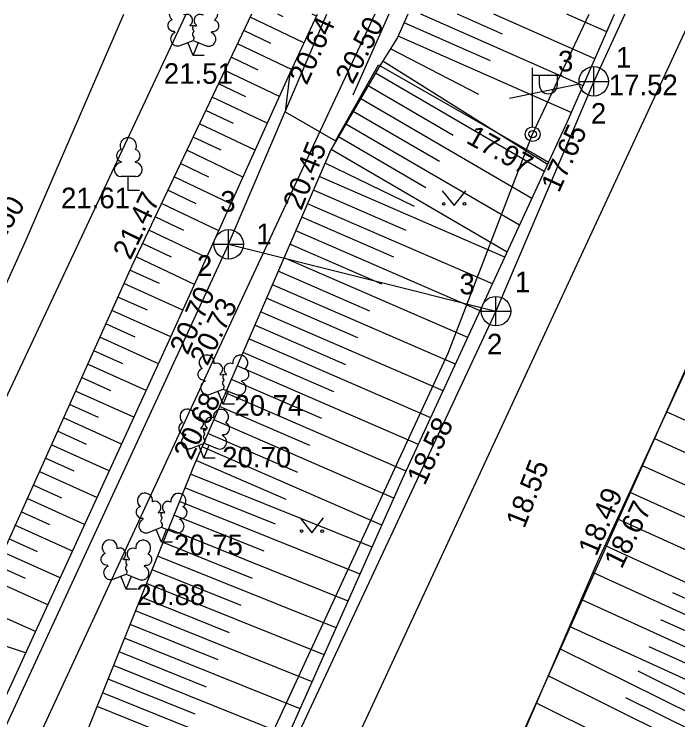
# Model space of a CAD drawing. Extents: x 714391 to 714584, y 6589993 to 6590151.
# Drawn here: x 714448.93 to 714471.46, y 6590127.12 to 6590151.08 of the extents above; entities that cross this region are included whole.
import ezdxf

# ---------------------------------------------------------------- set-up
doc = ezdxf.new("R2010")
doc.units = 0
for name, color, linetype in [('AED', 7, 'Continuous'), ('HALJASTUS', 7, 'Continuous'), ('HOONE', 7, 'Continuous'), ('KKAEV', 7, 'Continuous'), ('KORGUS', 7, 'Continuous'), ('KTRASS', 7, 'Continuous'), ('MPKAABEL', 7, 'Continuous'), ('POST', 7, 'Continuous'), ('PUU', 7, 'Continuous'), ('RELJEEF', 7, 'Continuous'), ('SITRASS', 7, 'Continuous'), ('SKTRASS', 7, 'Continuous'), ('TEE', 7, 'Continuous'), ('TORU NR', 7, 'Continuous')]:
    doc.layers.add(name, color=color, linetype=linetype)

msp = doc.modelspace()

# ---------------------------------------------------------------- linework, layer by layer
at = {"layer": 'AED'}
for points in [[(714442.826, 6590125.646), (714454.774, 6590151.075)], [(714461.649, 6590151.075), (714460.43, 6590148.33)]]:
    msp.add_lwpolyline(points, dxfattribs=at)
at = {"layer": 'HALJASTUS'}
for p, q in [((714463.459, 6590145.083), (714463.864, 6590144.578)), ((714463.864, 6590144.578), (714464.259, 6590145.083)), ((714458.635, 6590133.981), (714459.04, 6590133.476)), ((714459.04, 6590133.476), (714459.435, 6590133.981))]:
    msp.add_line(p, q, dxfattribs=at)
for centre, radius in [((714463.511, 6590144.634), 0.0428), ((714464.211, 6590144.634), 0.0452), ((714458.687, 6590133.531), 0.0428), ((714459.387, 6590133.531), 0.0452)]:
    msp.add_circle(centre, radius, dxfattribs=at)
at = {"layer": 'HOONE'}
msp.add_lwpolyline([(714462.081, 6590095.105), (714459.73, 6590096.05), (714433.74, 6590109.31), (714441.36, 6590125.77), (714449.34, 6590143.41), (714452.652, 6590151.075)], dxfattribs=at)
at = {"layer": 'KKAEV'}
for p, q in [((714468.603, 6590148.293), (714468.603, 6590149.293)), ((714468.103, 6590148.793), (714469.103, 6590148.793)), ((714456.211, 6590142.764), (714456.211, 6590143.764)), ((714455.711, 6590143.264), (714456.711, 6590143.264)), ((714465.284, 6590140.494), (714465.284, 6590141.494)), ((714464.784, 6590140.994), (714465.784, 6590140.994))]:
    msp.add_line(p, q, dxfattribs=at)
for centre in [(714468.603, 6590148.793), (714456.211, 6590143.264), (714465.284, 6590140.994)]:
    msp.add_circle(centre, 0.5, dxfattribs=at)
at = {"layer": 'KTRASS'}
for p, q in [((714456.211, 6590143.264), (714459.543, 6590151.075)), ((714469.654, 6590151.075), (714468.603, 6590148.793)), ((714468.603, 6590148.793), (714465.284, 6590140.994)), ((714468.113, 6590148.694), (714465.744, 6590148.214)), ((714456.211, 6590143.264), (714438.594, 6590105.207)), ((714456.211, 6590143.264), (714465.284, 6590140.994)), ((714465.284, 6590140.994), (714455.022, 6590119.06))]:
    msp.add_line(p, q, dxfattribs=at)
at = {"layer": 'MPKAABEL'}
msp.add_lwpolyline([(714394.611, 6589992.711), (714400.19, 6590004.938), (714412.114, 6590031.265), (714423.696, 6590056.183), (714434.84, 6590082.35), (714435.599, 6590083.495), (714435.59, 6590083.97), (714441.1, 6590097.08), (714442.02, 6590098.72), (714442.75, 6590099.35), (714444.22, 6590100.41), (714445.54, 6590101.3), (714446.63, 6590102.41), (714450.168, 6590111.053), (714453.153, 6590116.846), (714463.66, 6590139.57), (714466.53, 6590147), (714468.444, 6590151.075)], dxfattribs=at)
at = {"layer": 'POST'}
for p, q in [((714466.53, 6590147.25), (714466.53, 6590149.25)), ((714466.53, 6590149), (714467.53, 6590149)), ((714466.757, 6590148.679), (714466.757, 6590149)), ((714467.369, 6590148.679), (714467.369, 6590149)), ((714466.53, 6590147), (714466.53, 6590147))]:
    msp.add_line(p, q, dxfattribs=at)
for radius in [0.25, 0.127]:
    msp.add_circle((714466.53, 6590147), radius, dxfattribs=at)
msp.add_arc((714467.063, 6590148.679), 0.306, 180, 0, dxfattribs=at)
at = {"layer": 'PUU'}
for p, q in [((714454.92, 6590150.664), (714454.905, 6590150.699)), ((714455.105, 6590150.659), (714455.12, 6590150.699)), ((714454.39, 6590150.454), (714454.375, 6590150.494)), ((714455.63, 6590150.444), (714455.645, 6590150.484)), ((714454.565, 6590150.009), (714455.01, 6590150.184)), ((714455.005, 6590149.674), (714454.83, 6590150.114)), ((714455.005, 6590149.674), (714455.185, 6590150.114)), ((714455.01, 6590150.184), (714455.45, 6590150.004)), ((714455.385, 6590149.674), (714455.005, 6590149.674)), ((714452.566, 6590146.064), (714452.566, 6590146.034)), ((714453.046, 6590146.064), (714453.046, 6590146.034)), ((714453.046, 6590145.559), (714452.566, 6590145.559)), ((714452.806, 6590145.084), (714452.806, 6590145.559)), ((714453.186, 6590145.084), (714452.806, 6590145.084)), ((714455.94, 6590138.827), (714455.925, 6590138.862)), ((714456.125, 6590138.822), (714456.14, 6590138.862)), ((714455.41, 6590138.617), (714455.395, 6590138.657)), ((714456.65, 6590138.607), (714456.665, 6590138.647)), ((714455.585, 6590138.172), (714456.03, 6590138.347)), ((714456.025, 6590137.837), (714455.85, 6590138.277)), ((714456.025, 6590137.837), (714456.205, 6590138.277)), ((714456.03, 6590138.347), (714456.47, 6590138.167)), ((714456.405, 6590137.837), (714456.025, 6590137.837)), ((714455.288, 6590136.992), (714455.273, 6590137.027)), ((714455.473, 6590136.987), (714455.488, 6590137.027)), ((714454.758, 6590136.782), (714454.743, 6590136.822)), ((714455.998, 6590136.772), (714456.013, 6590136.812)), ((714454.933, 6590136.337), (714455.378, 6590136.512)), ((714455.378, 6590136.512), (714455.818, 6590136.332)), ((714455.373, 6590136.002), (714455.198, 6590136.442)), ((714455.373, 6590136.002), (714455.553, 6590136.442)), ((714455.753, 6590136.002), (714455.373, 6590136.002)), ((714453.843, 6590134.14), (714453.828, 6590134.175)), ((714454.028, 6590134.135), (714454.043, 6590134.175)), ((714453.313, 6590133.93), (714453.298, 6590133.97)), ((714454.553, 6590133.92), (714454.568, 6590133.96)), ((714453.488, 6590133.485), (714453.933, 6590133.66)), ((714453.928, 6590133.15), (714453.753, 6590133.59)), ((714453.928, 6590133.15), (714454.108, 6590133.59)), ((714453.933, 6590133.66), (714454.373, 6590133.48)), ((714454.308, 6590133.15), (714453.928, 6590133.15)), ((714452.117, 6590132.341), (714452.102, 6590132.381)), ((714452.647, 6590132.551), (714452.632, 6590132.586)), ((714452.832, 6590132.546), (714452.847, 6590132.586)), ((714453.357, 6590132.331), (714453.372, 6590132.371)), ((714452.292, 6590131.896), (714452.737, 6590132.071)), ((714452.732, 6590131.561), (714452.557, 6590132.001)), ((714452.732, 6590131.561), (714452.912, 6590132.001)), ((714452.737, 6590132.071), (714453.177, 6590131.891)), ((714453.112, 6590131.561), (714452.732, 6590131.561))]:
    msp.add_line(p, q, dxfattribs=at)
for points in [[(714455.01, 6590150.679), (714454.99, 6590150.604), (714454.99, 6590150.584), (714455, 6590150.554), (714455.02, 6590150.519), (714455.025, 6590150.499), (714455.01, 6590150.464), (714454.985, 6590150.414), (714454.98, 6590150.389), (714454.985, 6590150.374), (714454.995, 6590150.344), (714455.03, 6590150.284), (714455.035, 6590150.264), (714455.03, 6590150.244), (714455.015, 6590150.209), (714455.01, 6590150.184)], [(714456.03, 6590138.842), (714456.01, 6590138.767), (714456.01, 6590138.747), (714456.02, 6590138.717), (714456.04, 6590138.682), (714456.045, 6590138.662), (714456.03, 6590138.627), (714456.005, 6590138.577), (714456, 6590138.552), (714456.005, 6590138.537), (714456.015, 6590138.507), (714456.05, 6590138.447), (714456.055, 6590138.427), (714456.05, 6590138.407), (714456.035, 6590138.372), (714456.03, 6590138.347)], [(714455.378, 6590137.007), (714455.358, 6590136.932), (714455.358, 6590136.912), (714455.368, 6590136.882), (714455.388, 6590136.847), (714455.393, 6590136.827), (714455.378, 6590136.792), (714455.353, 6590136.742), (714455.348, 6590136.717), (714455.353, 6590136.702), (714455.363, 6590136.672), (714455.398, 6590136.612), (714455.403, 6590136.592), (714455.398, 6590136.572), (714455.383, 6590136.537), (714455.378, 6590136.512)], [(714453.933, 6590134.155), (714453.913, 6590134.08), (714453.913, 6590134.06), (714453.923, 6590134.03), (714453.943, 6590133.995), (714453.948, 6590133.975), (714453.933, 6590133.94), (714453.908, 6590133.89), (714453.903, 6590133.865), (714453.908, 6590133.85), (714453.918, 6590133.82), (714453.953, 6590133.76), (714453.958, 6590133.74), (714453.953, 6590133.72), (714453.938, 6590133.685), (714453.933, 6590133.66)], [(714452.737, 6590132.566), (714452.717, 6590132.491), (714452.717, 6590132.471), (714452.727, 6590132.441), (714452.747, 6590132.406), (714452.752, 6590132.386), (714452.737, 6590132.351), (714452.712, 6590132.301), (714452.707, 6590132.276), (714452.712, 6590132.261), (714452.722, 6590132.231), (714452.757, 6590132.171), (714452.762, 6590132.151), (714452.757, 6590132.131), (714452.742, 6590132.096), (714452.737, 6590132.071)]]:
    msp.add_lwpolyline(points, dxfattribs=at)
for centre, radius, start, end in [((714454.448, 6590151.088), 0.256, 182.852, 232.5173), ((714454.448, 6590151.088), 0.256, 350.4856, 357.148), ((714454.791, 6590150.866), 0.202, 305.1345, 116.705), ((714455.238, 6590150.862), 0.202, 62.412, 233.9825), ((714455.584, 6590151.079), 0.256, 180.8901, 188.6314), ((714455.584, 6590151.079), 0.256, 306.5997, 359.1099), ((714454.349, 6590150.692), 0.202, 106.2979, 277.8684), ((714455.677, 6590150.682), 0.202, 261.2486, 72.8191), ((714455.009, 6590150.441), 0.237, 66.7655, 111.5015), ((714454.479, 6590150.232), 0.237, 111.5014, 291.5004), ((714455.54, 6590150.224), 0.237, 247.6166, 67.6155), ((714452.806, 6590146.604), 0.277, 332.5799, 207.4201), ((714452.616, 6590146.272), 0.212, 105.2441, 257.079), ((714452.996, 6590146.272), 0.212, 282.921, 74.7559), ((714452.568, 6590145.797), 0.237, 90, 270), ((714453.043, 6590145.797), 0.237, 270, 90), ((714455.468, 6590139.251), 0.256, 111.5027, 232.5173), ((714455.468, 6590139.251), 0.256, 350.4856, 111.5002), ((714456.604, 6590139.242), 0.256, 67.6168, 188.6314), ((714456.604, 6590139.242), 0.256, 306.5997, 67.6143), ((714455.811, 6590139.029), 0.202, 305.1345, 116.705), ((714456.258, 6590139.025), 0.202, 62.412, 233.9825), ((714455.369, 6590138.855), 0.202, 106.2979, 277.8684), ((714456.029, 6590138.604), 0.237, 66.7655, 111.5015), ((714456.697, 6590138.845), 0.202, 261.2486, 72.8191), ((714455.499, 6590138.395), 0.237, 111.5014, 291.5004), ((714456.56, 6590138.387), 0.237, 247.6166, 67.6155), ((714454.816, 6590137.416), 0.256, 111.5027, 232.5173), ((714454.816, 6590137.416), 0.256, 350.4856, 111.5002), ((714455.952, 6590137.407), 0.256, 67.6168, 188.6314), ((714455.952, 6590137.407), 0.256, 306.5997, 67.6143), ((714454.717, 6590137.02), 0.202, 106.2979, 277.8684), ((714455.159, 6590137.194), 0.202, 305.1345, 116.705), ((714455.606, 6590137.19), 0.202, 62.412, 233.9825), ((714456.045, 6590137.01), 0.202, 261.2486, 72.8191), ((714455.377, 6590136.769), 0.237, 66.7655, 111.5015), ((714454.847, 6590136.56), 0.237, 111.5014, 291.5004), ((714455.908, 6590136.552), 0.237, 247.6166, 67.6155), ((714453.371, 6590134.564), 0.256, 111.5027, 232.5173), ((714453.371, 6590134.564), 0.256, 350.4856, 111.5002), ((714454.507, 6590134.555), 0.256, 67.6168, 188.6314), ((714454.507, 6590134.555), 0.256, 306.5997, 67.6143), ((714453.714, 6590134.342), 0.202, 305.1345, 116.705), ((714454.161, 6590134.338), 0.202, 62.412, 233.9825), ((714453.272, 6590134.168), 0.202, 106.2979, 277.8684), ((714454.6, 6590134.158), 0.202, 261.2486, 72.8191), ((714453.932, 6590133.917), 0.237, 66.7655, 111.5015), ((714453.402, 6590133.708), 0.237, 111.5014, 291.5004), ((714454.463, 6590133.7), 0.237, 247.6166, 67.6155), ((714452.175, 6590132.975), 0.256, 111.5027, 232.5173), ((714452.175, 6590132.975), 0.256, 350.4856, 111.5002), ((714453.311, 6590132.966), 0.256, 67.6168, 188.6314), ((714453.311, 6590132.966), 0.256, 306.5997, 67.6143), ((714452.518, 6590132.753), 0.202, 305.1345, 116.705), ((714452.965, 6590132.749), 0.202, 62.412, 233.9825), ((714452.076, 6590132.579), 0.202, 106.2979, 277.8684), ((714453.404, 6590132.569), 0.202, 261.2486, 72.8191), ((714452.736, 6590132.328), 0.237, 66.7655, 111.5015), ((714452.206, 6590132.119), 0.237, 111.5014, 291.5004), ((714453.267, 6590132.111), 0.237, 247.6166, 67.6155)]:
    msp.add_arc(centre, radius, start, end, dxfattribs=at)
at = {"layer": 'RELJEEF'}
for p, q in [((714458.066, 6590150.986), (714457.878, 6590151.075)), ((714459.19, 6590151.006), (714459.043, 6590151.075)), ((714468.242, 6590148.646), (714462.74, 6590151.075)), ((714465.506, 6590150.4), (714463.977, 6590151.075)), ((714468.645, 6590149.561), (714465.215, 6590151.075)), ((714469.048, 6590150.476), (714467.691, 6590151.075)), ((714458.768, 6590150.099), (714456.938, 6590150.969)), ((714465.103, 6590149.485), (714462.166, 6590150.782)), ((714457.64, 6590150.081), (714456.724, 6590150.517)), ((714467.839, 6590147.731), (714461.964, 6590150.325)), ((714458.346, 6590149.192), (714456.509, 6590150.065)), ((714464.707, 6590148.346), (714461.705, 6590149.898)), ((714457.217, 6590149.176), (714456.294, 6590149.614)), ((714467.036, 6590145.974), (714461.44, 6590149.474)), ((714457.933, 6590148.282), (714456.08, 6590149.162)), ((714466.924, 6590145.733), (714461.196, 6590149.069)), ((714456.796, 6590148.268), (714455.865, 6590148.711)), ((714463.829, 6590146.957), (714460.945, 6590148.637)), ((714457.521, 6590147.37), (714455.651, 6590148.259)), ((714466.504, 6590144.821), (714460.693, 6590148.205)), ((714456.376, 6590147.361), (714455.436, 6590147.808)), ((714463.367, 6590146.069), (714460.441, 6590147.773)), ((714457.109, 6590146.459), (714455.221, 6590147.356)), ((714466.083, 6590143.909), (714460.19, 6590147.341)), ((714455.955, 6590146.454), (714455.007, 6590146.904)), ((714462.905, 6590145.181), (714459.938, 6590146.909)), ((714456.698, 6590145.547), (714454.792, 6590146.453)), ((714465.662, 6590142.997), (714459.686, 6590146.477)), ((714455.535, 6590145.546), (714454.577, 6590146.001)), ((714462.515, 6590144.547), (714459.487, 6590146.018)), ((714456.286, 6590144.635), (714454.363, 6590145.55)), ((714465.584, 6590142.828), (714459.288, 6590145.559)), ((714455.114, 6590144.639), (714454.148, 6590145.098)), ((714462.232, 6590143.737), (714459.089, 6590145.101)), ((714455.874, 6590143.724), (714453.934, 6590144.646)), ((714465.165, 6590141.92), (714458.89, 6590144.642)), ((714454.694, 6590143.732), (714453.719, 6590144.195)), ((714461.823, 6590142.824), (714458.691, 6590144.183)), ((714455.463, 6590142.812), (714453.504, 6590143.743)), ((714464.746, 6590141.011), (714458.492, 6590143.725)), ((714454.273, 6590142.824), (714453.29, 6590143.292)), ((714461.415, 6590141.911), (714458.293, 6590143.266)), ((714455.051, 6590141.901), (714453.075, 6590142.84)), ((714464.327, 6590140.103), (714458.094, 6590142.807)), ((714453.863, 6590141.936), (714452.863, 6590142.387)), ((714461.006, 6590140.999), (714457.895, 6590142.348)), ((714454.657, 6590141.03), (714452.658, 6590141.931)), ((714463.908, 6590139.195), (714457.696, 6590141.89)), ((714453.452, 6590141.025), (714452.452, 6590141.475)), ((714460.598, 6590140.086), (714457.497, 6590141.431)), ((714454.246, 6590140.119), (714452.247, 6590141.02)), ((714463.489, 6590138.286), (714457.298, 6590140.972)), ((714453.04, 6590140.114), (714452.042, 6590140.564)), ((714460.189, 6590139.173), (714457.099, 6590140.514)), ((714453.83, 6590139.209), (714451.836, 6590140.108)), ((714463.07, 6590137.378), (714456.9, 6590140.055)), ((714452.626, 6590139.203), (714451.631, 6590139.652)), ((714459.781, 6590138.26), (714456.701, 6590139.596)), ((714453.413, 6590138.301), (714451.425, 6590139.196)), ((714462.651, 6590136.47), (714456.502, 6590139.138)), ((714452.212, 6590138.293), (714451.22, 6590138.74)), ((714459.372, 6590137.347), (714456.303, 6590138.679)), ((714452.995, 6590137.392), (714451.014, 6590138.284)), ((714462.232, 6590135.562), (714456.104, 6590138.22)), ((714451.798, 6590137.383), (714450.809, 6590137.829)), ((714458.965, 6590136.434), (714455.905, 6590137.762)), ((714471.087, 6590137.576), (714476.058, 6590135.315)), ((714452.578, 6590136.483), (714450.603, 6590137.373)), ((714461.822, 6590134.65), (714455.706, 6590137.303)), ((714451.383, 6590136.473), (714450.398, 6590136.917)), ((714458.563, 6590135.518), (714455.507, 6590136.844)), ((714452.16, 6590135.574), (714450.193, 6590136.461)), ((714470.668, 6590136.669), (714475.644, 6590134.405)), ((714461.415, 6590133.736), (714455.308, 6590136.386)), ((714450.969, 6590135.563), (714449.987, 6590136.005)), ((714458.16, 6590134.603), (714455.109, 6590135.927)), ((714470.248, 6590135.761), (714475.23, 6590133.495)), ((714451.743, 6590134.666), (714449.782, 6590135.549)), ((714461.081, 6590132.986), (714454.917, 6590135.465)), ((714450.555, 6590134.652), (714449.576, 6590135.094)), ((714457.804, 6590133.765), (714454.73, 6590135.001)), ((714469.829, 6590134.853), (714474.816, 6590132.584)), ((714451.325, 6590133.757), (714449.371, 6590134.638)), ((714460.674, 6590132.072), (714454.544, 6590134.537)), ((714450.141, 6590133.742), (714449.165, 6590134.182)), ((714457.414, 6590132.844), (714454.357, 6590134.074)), ((714469.41, 6590133.945), (714474.402, 6590131.674)), ((714450.908, 6590132.848), (714448.96, 6590133.726)), ((714460.267, 6590131.157), (714454.171, 6590133.61)), ((714449.727, 6590132.832), (714448.755, 6590133.27)), ((714457.024, 6590131.923), (714453.984, 6590133.146)), ((714468.99, 6590133.037), (714473.988, 6590130.764)), ((714450.49, 6590131.939), (714448.549, 6590132.814)), ((714459.86, 6590130.243), (714453.797, 6590132.682)), ((714449.313, 6590131.922), (714448.344, 6590132.358)), ((714456.634, 6590131.002), (714453.611, 6590132.218)), ((714450.073, 6590131.031), (714448.138, 6590131.903)), ((714468.581, 6590132.125), (714473.574, 6590129.854)), ((714459.453, 6590129.329), (714453.424, 6590131.754)), ((714471.281, 6590131.446), (714473.781, 6590130.309)), ((714456.244, 6590130.081), (714453.238, 6590131.29)), ((714468.184, 6590131.207), (714473.16, 6590128.943)), ((714449.655, 6590130.122), (714447.727, 6590130.991)), ((714459.046, 6590128.415), (714453.051, 6590130.826)), ((714470.874, 6590130.532), (714473.367, 6590129.398)), ((714455.854, 6590129.16), (714452.864, 6590130.363)), ((714467.787, 6590130.289), (714472.746, 6590128.033)), ((714449.321, 6590129.394), (714447.366, 6590130.06)), ((714458.64, 6590127.501), (714452.678, 6590129.899)), ((714467.46, 6590129.534), (714472.314, 6590127.131)), ((714470.469, 6590129.618), (714472.953, 6590128.488)), ((714455.464, 6590128.239), (714452.491, 6590129.435)), ((714458.233, 6590126.587), (714452.305, 6590128.971)), ((714470.098, 6590128.786), (714472.536, 6590127.579)), ((714467.063, 6590128.615), (714471.871, 6590126.235)), ((714455.074, 6590127.318), (714452.118, 6590128.507)), ((714457.826, 6590125.672), (714451.932, 6590128.043)), ((714469.677, 6590127.879), (714472.092, 6590126.683)), ((714466.666, 6590127.696), (714471.427, 6590125.339)), ((714454.684, 6590126.397), (714451.745, 6590127.579))]:
    msp.add_line(p, q, dxfattribs=at)
for points in [[(714456.989, 6590151.075), (714452.93, 6590142.535), (714447.548, 6590130.593), (714445.216, 6590123.75), (714445.225, 6590120.478)], [(714462.295, 6590151.075), (714461.943, 6590150.278), (714461.322, 6590149.285)], [(714461.322, 6590149.285), (714459.685, 6590146.474), (714455.021, 6590135.724), (714449.023, 6590120.812), (714449.282, 6590112.11)]]:
    msp.add_lwpolyline(points, dxfattribs=at)
at = {"layer": 'SITRASS'}
msp.add_line((714445.318, 6590093.669), (714471.983, 6590151.075), dxfattribs=at)
at = {"layer": 'SKTRASS'}
msp.add_line((714458.254, 6590108.91), (714474.359, 6590144.932), dxfattribs=at)
at = {"layer": 'TEE'}
for points in [[(714431.863, 6590102.016), (714435.225, 6590099.219), (714445.225, 6590120.478), (714454.134, 6590139.871), (714458.283, 6590149.057), (714459.223, 6590151.075)], [(714461.172, 6590151.075), (714459.316, 6590147.116), (714455.509, 6590138.934), (714446.669, 6590119.883), (714437.663, 6590099.797), (714438.254, 6590097.927), (714442.53, 6590099.149)], [(714450.542, 6590109.47), (714454.553, 6590118.32), (714462.112, 6590135.302), (714467.698, 6590147.41), (714469.311, 6590151.075)], [(714583.92, 6590101.143), (714565.419, 6590101.225), (714549.748, 6590101.3), (714530.696, 6590101.382), (714516.957, 6590101.382), (714497.906, 6590101.442), (714488.527, 6590101.467), (714476.238, 6590101.479), (714465.964, 6590101.492), (714465.149, 6590101.593), (714461.989, 6590102.308), (714461.271, 6590102.628), (714460.534, 6590103.105), (714459.97, 6590103.737), (714459.406, 6590104.596), (714458.782, 6590106.528), (714458.59, 6590109.02), (714468.756, 6590132.53), (714474.437, 6590144.828), (714474.939, 6590145.152), (714475.17, 6590145.792), (714474.999, 6590146.077), (714477.095, 6590151.075)], [(714458.283, 6590149.057), (714458.127, 6590147.76), (714459.836, 6590146.771), (714461.293, 6590149.354), (714466.663, 6590146.285), (714467.071, 6590146.052)]]:
    msp.add_lwpolyline(points, dxfattribs=at)

# ---------------------------------------------------------------- texts
at = {"layer": 'KORGUS'}
for s, rotation, p in [('20.64', 65.2918, (714458.863, 6590148.641)), ('20.50', 62.4142, (714460.416, 6590148.663)), ('17.65', 65.505, (714467.419, 6590144.986)), ('17.97', 330.7808, (714464.235, 6590146.726)), ('20.45', 68.1986, (714458.678, 6590144.385)), ('21.47', 63.9642, (714452.875, 6590142.704)), ('20.70', 66.3179, (714454.823, 6590139.477)), ('20.73', 63.8292, (714455.489, 6590139.107)), ('20.68', 64.4036, (714454.945, 6590135.902)), ('18.58', 65.0715, (714462.865, 6590135.049)), ('18.55', 68.6833, (714466.248, 6590133.592)), ('18.49', 67.1042, (714468.691, 6590132.647)), ('18.67', 63.6767, (714469.547, 6590132.218))]:
    msp.add_text(s, height=0.7, rotation=rotation, dxfattribs=at).set_placement(p)
for s, p in [('21.51', (714454.013, 6590148.71)), ('17.52', (714469.113, 6590148.323)), ('21.61', (714450.522, 6590144.486)), ('20.74', (714456.405, 6590137.444)), ('20.70', (714455.994, 6590135.689)), ('20.75', (714454.354, 6590132.712)), ('20.88', (714453.078, 6590131.02))]:
    msp.add_text(s, height=0.7, dxfattribs=at).set_placement(p)
at = {"layer": 'TORU NR'}
for s, p in [('1', (714469.357, 6590149.263)), ('3', (714467.391, 6590149.131)), ('2', (714468.506, 6590147.356)), ('3', (714455.928, 6590144.371)), ('1', (714457.151, 6590143.268)), ('2', (714455.136, 6590142.189)), ('3', (714464.045, 6590141.566)), ('1', (714465.927, 6590141.638)), ('2', (714464.98, 6590139.527))]:
    msp.add_text(s, height=0.7, dxfattribs=at).set_placement(p)
msp.add_text('ø150', height=0.7, rotation=58.1611, dxfattribs=at).set_placement((714448.203, 6590142.804))

doc.saveas('drawing.dxf')
